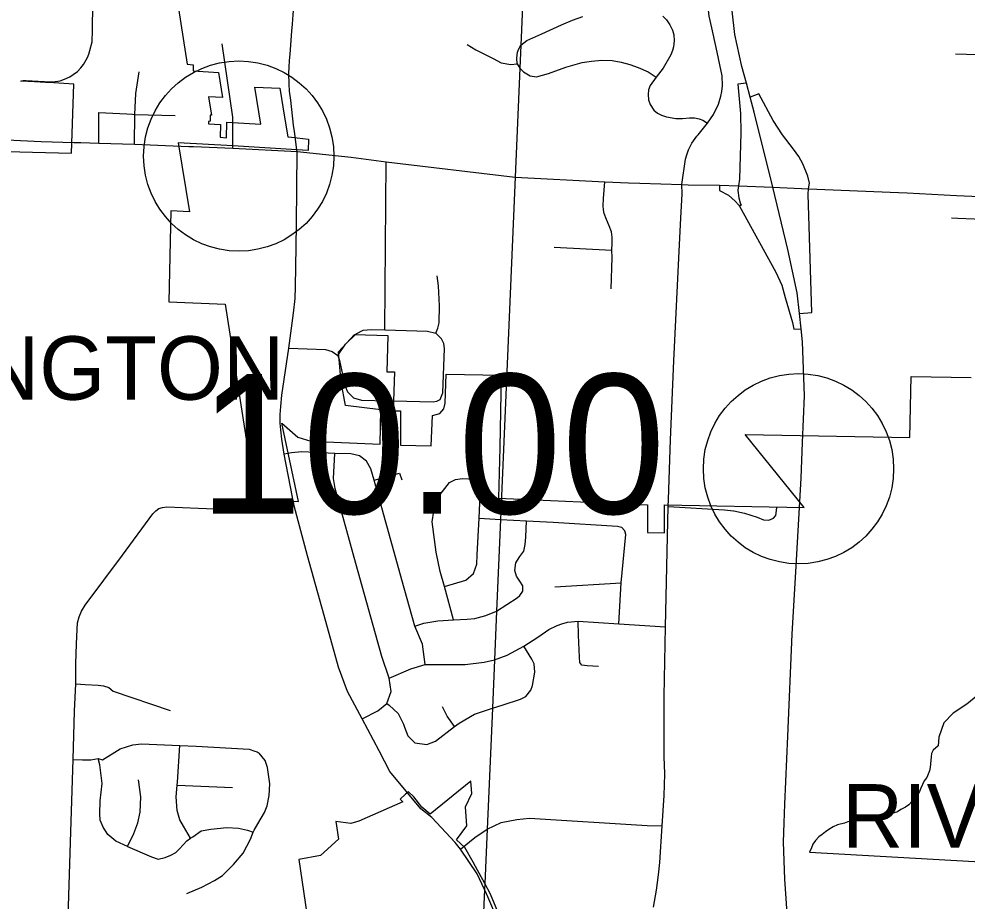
# Model space of a CAD drawing. Extents: x 1729596 to 1934326, y 644115 to 911751.
# Drawn here: x 1812555 to 1820031, y 755846 to 762800 of the extents above; entities that cross this region are included whole.
import ezdxf

# ---------------------------------------------------------------- set-up
doc = ezdxf.new("R2010")
doc.units = 0
for name, color, linetype in [('Default', 7, 'Continuous'), ('GM_X_City_Street', 7, 'Continuous'), ('GM_X_Corporation', 7, 'Continuous'), ('GM_X_Corporation_Text', 7, 'Continuous'), ('GM_X_County_Road', 7, 'Continuous'), ('GM_X_Interchange_Ramps', 7, 'Continuous'), ('GM_X_State_Route', 7, 'Continuous'), ('GM_X_Township', 7, 'Continuous')]:
    doc.layers.add(name, color=color, linetype=linetype)

msp = doc.modelspace()

# ---------------------------------------------------------------- linework, layer by layer
at = {"layer": 'Default'}
for centre in [(1814288, 761719.4), (1818701.8, 759254.1)]:
    msp.add_circle(centre, 750, dxfattribs=at)
at = {"layer": 'GM_X_City_Street'}
for points in [[(1814710.8, 762758.6), (1814716.8, 762832.9), (1814730.6, 763010.5), (1814750.5, 763263.9), (1814758.1, 763336.9), (1814767.3, 763401.8), (1814781.1, 763473.7), (1814798, 763550.3), (1814836.8, 763686.7), (1814871.5, 763796.5), (1814939.9, 763985.4), (1814999.2, 764179.5), (1815163.6, 764672.8), (1815272.9, 764996.6), (1815338.3, 765194.7), (1815458.8, 765550.1), (1815603.2, 765932.7), (1815765.2, 766360), (1815831.4, 766554.7), (1815848.4, 766601.2), (1815849.4, 766604.8)], [(1817910, 761888.1), (1817983.1, 761980.2), (1818032.5, 762047.7), (1818069.8, 762128.4), (1818090.3, 762192.3), (1818096.3, 762229.6), (1818101.2, 762274.2), (1818098.7, 762352.6), (1818053, 762574.3), (1818019.2, 762729.8), (1817997.2, 762822.6), (1817990.4, 762892.8), (1817983.7, 763045.3), (1817993.1, 763139.8), (1818006.6, 763245.1), (1818035, 763373.3), (1818070.1, 763478.6), (1818102.5, 763556.9), (1818143, 763651.4), (1818174, 763748.5), (1818188.9, 763818.7), (1818205.6, 763899.8)], [(1816089.3, 762599), (1816158, 762557.3), (1816294.5, 762488.4), (1816357.2, 762455.7), (1816432.3, 762442.4), (1816483.5, 762447.8), (1816480, 762491), (1816486.1, 762537.8), (1816495.8, 762565.2), (1816511.6, 762593.6), (1816558.5, 762630.5), (1816676.9, 762682.6), (1816834, 762754.2), (1816919.4, 762791.7), (1817001.6, 762820.8)], [(1817632.8, 762821.9), (1817662, 762792.7), (1817687, 762753.1), (1817707.8, 762712.5), (1817718.2, 762676.1), (1817721.3, 762629.2), (1817717.2, 762580.3), (1817708.8, 762551.1), (1817696.3, 762517.8), (1817634.9, 762411.5), (1817579.3, 762341.7), (1817532.3, 762276.7), (1817517.9, 762241.7), (1817515.4, 762205.5), (1817520.2, 762162.2), (1817532.3, 762127.2), (1817561.2, 762082.6), (1817589, 762058.5), (1817620.3, 762041.7), (1817661.3, 762028.4), (1817734.8, 762015.1), (1817787.8, 762015.1), (1817843.2, 762021.1), (1817881.8, 762019.9), (1817918, 762013.9), (1817948.1, 762001.9), (1817983.1, 761980.2)], [(1814727, 761914), (1814720.4, 761962.2), (1814697.5, 762160.2), (1814688.2, 762231.3), (1814684.6, 762289), (1814682.6, 762370.2), (1814685.1, 762420.2), (1814688.2, 762472.3), (1814692.4, 762524.2), (1814706.5, 762705.2), (1814710.8, 762758.6)], [(1819940.7, 762525.7), (1820458.6, 762508.6), (1820575.3, 762563.5), (1820627.5, 762581.1), (1820669.7, 762596.7), (1820725.7, 762596.1), (1820889.5, 762578.5), (1820921.7, 762590.2), (1820969.8, 762603.8), (1821034.1, 762627.1), (1821080.3, 762642.7), (1821182.3, 762635.7), (1821448.1, 762615.1), (1821480.2, 762618.8), (1821504.3, 762634.6), (1821531, 762625.1)], [(1814241.3, 761983.3), (1814242.5, 762026.5), (1814157.7, 762604.1)], [(1816483.5, 762447.8), (1816503.9, 762413.3), (1816532.1, 762382.4), (1816585, 762352.4), (1816634.5, 762345.3), (1816730.7, 762370), (1816866.7, 762419.5), (1816996.5, 762458.4), (1817070.4, 762468.8), (1817150.6, 762475), (1817231.8, 762471.9), (1817303.7, 762459.4), (1817372.4, 762441.7), (1817438.1, 762418.8), (1817516.2, 762384.5), (1817579.3, 762341.7)], [(1813487.2, 762281.2), (1813504, 762384.1)], [(1813464.9, 761812.9), (1813469.2, 762047.3), (1813476.2, 762213.1), (1813487.2, 762281.2)], [(1813184.5, 761820.7), (1813184.4, 762063.2), (1813405.9, 762052.5), (1813448.9, 762049)], [(1813448.9, 762049), (1813469.2, 762047.3), (1813786.9, 762038.6)], [(1814240, 761782.5), (1814240.2, 761799.1), (1814241.3, 761983.3)], [(1814748.7, 761756.5), (1814746.9, 761769.8), (1814727, 761914)], [(1815441, 760350.9), (1815449.3, 761673.2)], [(1817224.2, 760672.2), (1817231.4, 760920.7), (1817230, 760978.9), (1817232.1, 761032.1), (1817232.9, 761080.2), (1817227.8, 761121.5), (1817209.7, 761170.6), (1817186.5, 761219.6), (1817169.3, 761267.7), (1817163.3, 761296.1), (1817162.4, 761326.2), (1817164.1, 761385.6), (1817174.4, 761516.7)], [(1817677.2, 759011.5), (1817693.5, 759481.5), (1817719, 760106), (1817764.1, 761022.2), (1817774.2, 761230.2)], [(1819909.3, 761231.7), (1819957.7, 761229.8), (1820345.4, 761214.8), (1820685.1, 761201.6), (1820733.6, 761199.7)], [(1814714.8, 759012.1), (1814710.8, 759029.7), (1814646.4, 759369.7), (1814628.9, 759488.1), (1814618.8, 759560.8), (1814615.1, 759615.1), (1814614.2, 759681.4), (1814618.8, 759744), (1814628, 759835.1), (1814683.2, 760204.2), (1814720.1, 760482.2), (1814732.9, 760595.4), (1814736.6, 760688.3), (1814740.3, 761005.9), (1814742.3, 761183.5)], [(1816775, 761000.7), (1817230, 760978.9)], [(1815842.2, 760322.7), (1815858.2, 760362.1), (1815868.3, 760403.5), (1815871.3, 760539.1), (1815863, 760696), (1815852.8, 760774.2)], [(1815069.4, 760146.7), (1815129.7, 760236.3), (1815212.9, 760318.4), (1815269.9, 760346), (1815332.8, 760353.5), (1815441, 760350.9)], [(1815441, 760350.9), (1815775.7, 760339.2), (1815842.2, 760322.7)], [(1815876.8, 759801.5), (1815898.4, 759851.9), (1815910.2, 760201.2), (1815905.2, 760242.1), (1815887.5, 760279.4), (1815842.2, 760322.7)], [(1814683.2, 760204.2), (1814971.8, 760193.5), (1815024.8, 760178.9), (1815069.4, 760146.7), (1815081.8, 760108.6), (1815105.5, 759998.5), (1815120.4, 759923.2), (1815144.5, 759861.3), (1815191.9, 759813.4), (1815256.7, 759795.1), (1815462.8, 759789.9), (1815508.3, 759788.7)], [(1815508.3, 759788.7), (1815821.8, 759780.9), (1815851, 759786.8), (1815876.8, 759801.5)], [(1815758.8, 757711.2), (1815736.8, 757871.7), (1815676.2, 758014.1), (1815572.9, 758378.6), (1815356.8, 759164.9), (1815329.6, 759253.8), (1815294.6, 759314.2), (1815238.8, 759356.2), (1815171.1, 759373.2), (1815044.5, 759375.6), (1814784.4, 759386.7), (1814703.5, 759379.6), (1814646.4, 759369.7)], [(1815261.4, 757283.9), (1815384.1, 757345.9), (1815454.7, 757403.4), (1815489.1, 757498.5), (1815475, 757603.5), (1815415.2, 757773.6), (1815211.3, 758506.6), (1815047.4, 759098.6), (1815036.2, 759178.2), (1815044.5, 759375.6)], [(1815910.1, 758327), (1816079.3, 758377), (1816139.3, 758427.6), (1816164.5, 758501.9), (1816168.6, 758576.3), (1816182.7, 758865.2), (1816197.5, 759168.9), (1816200.5, 759228.3), (1816187, 759320.7)], [(1815356.8, 759164.9), (1815556.2, 759219.6), (1815573.2, 759166.7)], [(1815980.8, 758062.3), (1815910.1, 758327), (1815876.2, 758445.1), (1815845.5, 758597.1), (1815812.1, 758835.8), (1815839.4, 759004.3), (1815948.6, 759145), (1815996.4, 759170.9), (1816052.4, 759176.5), (1816197.5, 759168.9)], [(1812940.8, 755638.3), (1812963.4, 756391.7), (1812981.6, 756962.9), (1812993.7, 757342.2), (1813002.4, 757557.5), (1813003.3, 757719), (1813008.5, 757870.9), (1813013.7, 757988.9), (1813016.3, 758039.3), (1813029.3, 758086.1), (1813047.6, 758130.4), (1813077.1, 758179.9), (1813370.5, 758572.3), (1813610.1, 758897.8), (1813633, 758921.9), (1813658.1, 758941.5), (1813685.4, 758950.1), (1813722.1, 758953.3), (1813968.6, 758943.8), (1814165.6, 758936.8), (1814266.3, 758935.1), (1814384.4, 758940.3), (1814626.9, 758950.9), (1814725.5, 758961.1)], [(1815608.8, 756711.7), (1815478.6, 756868.5), (1815394.4, 757030.2), (1815261.4, 757283.9), (1815145.2, 757498.5), (1815075, 757688.9), (1814974, 758050.8), (1814830.5, 758568), (1814725.5, 758961.1), (1814718.6, 758995.9), (1814714.8, 759012.1)], [(1817642.5, 757216.3), (1817641.6, 757462.2), (1817653.5, 758007.1), (1817675.3, 758956.2), (1817677.2, 759011.5)], [(1817675.3, 758956.2), (1818119.1, 758930.7), (1818188.1, 758921.9)], [(1818188.1, 758921.9), (1818191.1, 758921.5), (1818276.7, 758903.3), (1818377, 758872.3), (1818426.2, 758850.5), (1818468.1, 758848.6), (1818504.5, 758865.1), (1818522.8, 758886.9), (1818531.9, 758947.1)], [(1815676.2, 758014.1), (1815747.6, 758036), (1815857.8, 758054.7), (1815980.8, 758062.3), (1816088, 758068.5), (1816148.9, 758075.1), (1816235.5, 758097.6), (1816320.6, 758132.9), (1816483.2, 758236.4), (1816504.9, 758254.1), (1816527.1, 758290.1), (1816527.2, 758332.3), (1816505.1, 758368.4), (1816477.5, 758406.3), (1816463.9, 758451.1), (1816471.7, 758511.5), (1816505.6, 758562.1), (1816536.1, 758605.9), (1816546.7, 758658.2), (1816550.6, 758715.7), (1816557.3, 758843.2)], [(1816182.7, 758865.2), (1816351.6, 758855.3), (1816557.3, 758843.2), (1816767.1, 758832.1), (1817275.5, 758801.8), (1817305.4, 758792.6), (1817333.6, 758765.3)], [(1817285.3, 758030.8), (1817302.6, 758354.3), (1817339, 758737), (1817333.6, 758765.3)], [(1816781.2, 758323.2), (1817302.6, 758354.3)], [(1815475, 757603.5), (1815644.9, 757677.4), (1815758.8, 757711.2), (1815996.4, 757711.9), (1816073.8, 757711.4), (1816224.2, 757729), (1816304.2, 757749), (1816403.3, 757784.1), (1816536.8, 757856.2), (1816645.9, 757927.2), (1816732.3, 757985.9), (1816798.4, 758018.3), (1816834.5, 758030.8), (1816880.7, 758044.5), (1816965.5, 758053.2), (1817285.3, 758030.8), (1817653.5, 758007.1)], [(1817123.8, 757695.2), (1817034, 757700.2), (1816992.9, 757705.2), (1816976.7, 757727.7), (1816975.4, 757770.1), (1816968, 757942.2), (1816965.5, 758053.2)], [(1815454.7, 757403.4), (1815474.6, 757390), (1815545.2, 757325.4), (1815588.2, 757239.8), (1815593.8, 757218.3), (1815622.5, 757148), (1815675.2, 757093.3), (1815771.2, 757079.5), (1815838.8, 757107.3), (1815988.8, 757221.5), (1816027.2, 757249.4), (1816147, 757319.7), (1816287.8, 757367.3), (1816373.8, 757393.4), (1816510, 757439), (1816550.6, 757458.8), (1816590.9, 757507.6), (1816603.6, 757546.8), (1816621.6, 757650.6), (1816618.4, 757716.3), (1816597.7, 757753.2), (1816536.8, 757856.2)], [(1813002.4, 757557.5), (1813078, 757553.2), (1813179.5, 757548), (1813220.3, 757543.6), (1813262.8, 757529.7), (1813298.4, 757502), (1813747.9, 757349.4)], [(1815988.8, 757221.5), (1815931.1, 757304.5), (1815895.8, 757377.3)], [(1817646.9, 756847.2), (1817647.1, 756850.8), (1817643.4, 756983.8), (1817642.5, 757216.3)], [(1812981.6, 756962.9), (1813055.4, 756958.6), (1813120.5, 756958.6), (1813178.7, 756969), (1813213.2, 756959.7), (1813352.8, 757045.4), (1813453.3, 757077.6), (1813521.4, 757086.4), (1813823.1, 757073.9), (1813952.9, 757068.5), (1814370.3, 757042.9), (1814416, 757028), (1814433.8, 757021.7), (1814447.7, 757013.4)], [(1813907.8, 756341.5), (1813851.2, 756437), (1813824.2, 756487.6), (1813803.5, 756560.1), (1813793.5, 756666.6), (1813801.5, 756758.7), (1813803.7, 756784.6), (1813823.1, 757073.9)], [(1814410, 756404.7), (1814439.3, 756454.4), (1814490.9, 756545.6), (1814511.9, 756597.4), (1814527.4, 756679.3), (1814533.1, 756771.3), (1814513.5, 756900), (1814496.5, 756954.4), (1814447.7, 757013.4)], [(1813410.4, 756276.7), (1813319.2, 756318.4), (1813256.2, 756369.7), (1813219.3, 756428.5), (1813196.4, 756483), (1813191.3, 756533.2), (1813195.2, 756637.4), (1813209.8, 756773.4), (1813191.7, 756920.3), (1813178.7, 756969)], [(1813410.4, 756276.7), (1813460.3, 756378), (1813491.9, 756463.6), (1813511.4, 756547.4), (1813515.6, 756667.6), (1813496.2, 756802.3)], [(1817559.5, 755797.1), (1817581.4, 755932.2), (1817597, 756053.4), (1817607.9, 756150), (1817627, 756438.9), (1817641.6, 756677.6), (1817646.9, 756847.2)], [(1813801.5, 756758.7), (1814238.7, 756742.6)], [(1816036.6, 756256.2), (1816149.4, 756347.5), (1816247, 756413.3), (1816357.5, 756465.8), (1816480.3, 756490.1), (1816580.6, 756498.7), (1817507.2, 756443.2), (1817627, 756438.9)], [(1813410.4, 756276.7), (1813598.8, 756195.1), (1813652.4, 756176.1), (1813706.6, 756189.1), (1813753, 756208.3), (1813791.4, 756229.7), (1813821.9, 756257.1), (1813879, 756322.3), (1813907.8, 756341.5), (1813925.6, 756353.5), (1813992.5, 756400.4), (1814068.6, 756413), (1814192.9, 756426.8), (1814284.7, 756421.1), (1814356.4, 756405.8), (1814401.8, 756388.5)], [(1813877.3, 755905.4), (1813998.1, 755955.3), (1814097.1, 756007.6), (1814159.8, 756046.6), (1814247.4, 756133.2), (1814323, 756224), (1814381, 756333.2), (1814401.8, 756388.5), (1814404.1, 756394.9), (1814409.6, 756404), (1814410, 756404.7)]]:
    msp.add_lwpolyline(points, dxfattribs=at)
at = {"layer": 'GM_X_Corporation'}
for points in [[(1813750.9, 763289.6), (1813882.1, 762443.2), (1813929.3, 762439.6), (1813929.7, 762390.5), (1814127.6, 762379.2), (1814159.2, 762182.5), (1814049.7, 762187.2), (1814072.5, 762041.2), (1814063.1, 762041.2), (1814063.5, 761993.5), (1814049.5, 761993.2), (1814048.7, 761973.2), (1814143, 761967.8), (1814140.9, 761867.9), (1814190.1, 761864.4), (1814193.8, 761985.9), (1814461.3, 761971.4), (1814413.7, 762261.8), (1814611, 762254.5), (1814648.4, 762025.9), (1814674.2, 761870.5), (1814702.7, 761868.9), (1814837.9, 761852.1), (1814834.3, 761763.6), (1814746.9, 761769.8), (1814240.2, 761799.1), (1813809, 761823), (1813899.4, 761280.9), (1813752.3, 761286.7), (1813736.5, 760570), (1814181.8, 760551.1), (1814422.1, 758999.2), (1814759.6, 758996.9), (1814627.7, 759613.2), (1814754.2, 759503.5), (1814855.4, 759472.2), (1815402, 759447.2), (1815409.1, 759719.6), (1815129.7, 759752.4), (1815096, 759937.5), (1815073.2, 760175.3), (1815200.2, 760311.5), (1815464.1, 760305.6), (1815454.3, 760018.9), (1815516.5, 760018.1), (1815505.5, 759711.7), (1815562.3, 759710.1), (1815562.3, 759440), (1815804.7, 759434), (1815814.6, 759675.1), (1815874.6, 759690.4), (1815904.8, 759726.1), (1815914.7, 759771.3), (1815924.1, 760000.8), (1816356.9, 759991.3), (1816345.4, 759420.7), (1816337.4, 759022.8), (1817510.2, 758970.3), (1817509.9, 758751.4), (1817644.9, 758748.2), (1817645.5, 758969.1), (1818746.1, 758949.3), (1818280.7, 759524.6), (1819580.5, 759501.3), (1819589.1, 759981.2), (1820064.5, 759972.7)], [(1811638.6, 761776), (1812968.8, 761741.5), (1812988, 762287.5), (1812830.6, 762297.3), (1812764.8, 762300.2), (1812678.5, 762305), (1812570.3, 762310.5), (1812576.6, 762312.4), (1812587.3, 762314), (1812597.9, 762314.3), (1812612.3, 762314.1), (1812802.9, 762304.7), (1812823.2, 762305.2), (1812878.8, 762312.8), (1812915.1, 762325.2), (1812956, 762343.3), (1812983.5, 762361.9), (1813016, 762387.3), (1813043.1, 762416.4), (1813064.1, 762442.2), (1813096, 762497.9), (1813105, 762523.3), (1813113.6, 762551.1), (1813131.6, 762620.5), (1813135, 762708.8), (1813138.3, 762922.9)], [(1820145.7, 757492.5), (1820030.2, 757399.6), (1819921.3, 757328.5), (1819848.6, 757251.1), (1819809, 757139.6), (1819802.4, 757071.1), (1819763.9, 757035.7), (1819751.7, 757009), (1819746.9, 756982.3), (1819742, 756929), (1819739.6, 756899.8), (1819734.7, 756873.2), (1819725, 756846.5), (1819712.9, 756819.8), (1819693.5, 756793.1), (1819679, 756764), (1819666.8, 756737.3), (1819657.1, 756710.7), (1819640.2, 756684), (1819623.2, 756657.3), (1819596.5, 756630.6), (1819572.2, 756603.9), (1819545.6, 756586.9), (1819509.2, 756567.5), (1819482.5, 756550.6), (1819455.8, 756540.8), (1819419.4, 756528.7), (1819392.8, 756516.6), (1819356.4, 756506.9), (1819329.7, 756499.6), (1819295.8, 756494.8), (1819266.7, 756492.3), (1819240, 756489.9), (1819210.9, 756487.5), (1819184.2, 756485), (1819157.5, 756482.6), (1819121.1, 756477.8), (1819092, 756470.5), (1819065.4, 756460.8), (1819009.6, 756446.2), (1818975.6, 756431.7), (1818941.7, 756409.8), (1818915, 756392.9), (1818888.3, 756371), (1818861.6, 756351.6), (1818834.9, 756322.5), (1818815.5, 756295.8), (1818803.4, 756266.7), (1818787.5, 756231.7), (1823340.6, 755973.2)], [(1816424, 755539.8), (1816273.4, 755900.9), (1816228.6, 755985), (1816155.5, 756119.7), (1816136.6, 756152.8), (1816070.5, 756268.4), (1816005.7, 756328.7), (1816085.9, 756439.8), (1816074.9, 756589.4), (1816125, 756693), (1816117.6, 756792.7), (1815797.9, 756531.8), (1815732.4, 756585.7), (1815668.4, 756668.7), (1815627.2, 756708.6), (1815603.7, 756689.9), (1815561.5, 756650), (1815581.8, 756627.9), (1815234, 756477.3), (1815171.7, 756458.9), (1815052.4, 756472.6), (1815075.4, 756334.5), (1814932.9, 756204.3), (1814760.8, 756172.7), (1815125, 753710)]]:
    msp.add_lwpolyline(points, dxfattribs=at)
at = {"layer": 'GM_X_County_Road'}
for points in [[(1817774.2, 761230.2), (1817783.4, 761421.4), (1817780.9, 761494.3), (1817810.6, 761693.9), (1817820.2, 761728.3), (1817835.4, 761769.2), (1817861.9, 761822.1), (1817899.9, 761875.3), (1817910, 761888.1)], [(1814742.3, 761183.5), (1814748.7, 761756.5)], [(1816250.9, 755880.5), (1816241.6, 755902.3), (1816226.5, 755936.1), (1816166.8, 756059.6), (1816036.6, 756256.2), (1815995.5, 756307.7), (1815809.7, 756505.9), (1815724.7, 756572.1), (1815608.8, 756711.7)], [(1816386.3, 755535.1), (1816327.4, 755701.6), (1816250.9, 755880.5)]]:
    msp.add_lwpolyline(points, dxfattribs=at)
at = {"layer": 'GM_X_Interchange_Ramps'}
for points in [[(1818290.4, 762293.7), (1818223.7, 762286.8), (1818243.6, 762054.9), (1818246.9, 761902.4), (1818237.3, 761538), (1818227.5, 761485.2)], [(1818781.8, 761462), (1818787.9, 761505.2), (1818775.4, 761561.7), (1818734.6, 761659), (1818704.8, 761715.5), (1818662.4, 761775.1), (1818574.5, 761888.1), (1818500.8, 761999.5), (1818389.4, 762209.8), (1818320.5, 762184.1)], [(1818077.8, 761489.5), (1818077.6, 761449.1), (1818148.7, 761412.1), (1818202.1, 761364.7), (1818231.7, 761333.5), (1818237, 761323.9), (1818522.1, 760803.2), (1818569.5, 760701), (1818597.6, 760604.7), (1818655.4, 760407.7), (1818665.8, 760354.4), (1818722.3, 760357.2)], [(1818227.5, 761485.2), (1818224, 761449.8), (1818224, 761449.2), (1818230, 761391.3), (1818242, 761350.7), (1818250.6, 761333.4), (1818237, 761323.9)], [(1818709.2, 760477.2), (1818806.4, 760487.4), (1818777.2, 761419.9), (1818781.8, 761462)]]:
    msp.add_lwpolyline(points, dxfattribs=at)
at = {"layer": 'GM_X_State_Route'}
for points in [[(1818498.5, 761474), (1818352.9, 762066.1), (1818320.5, 762184.1), (1818290.4, 762293.7), (1818254.5, 762424.5), (1818200.7, 762677), (1818178, 762864.4), (1818172.6, 763026.4), (1818179.4, 763166.8), (1818188.9, 763291), (1818222.6, 763462.4), (1818256.6, 763605.1), (1818316.8, 763840.3), (1818338.8, 763976), (1818348.5, 764167), (1818350.2, 764250.4), (1818357.7, 764939.8), (1818364, 765374.7), (1818382.6, 765736.3), (1818416.5, 766299.1)], [(1812348.4, 761852.1), (1812728.8, 761833.7), (1812988.5, 761826.9)], [(1812988.5, 761826.9), (1812992.7, 761826.8), (1813041.9, 761825.3)], [(1813041.9, 761825.3), (1813184.5, 761820.7), (1813464.9, 761812.9), (1813895.5, 761796.1)], [(1813895.5, 761796.1), (1813930.2, 761794.7), (1814240, 761782.5), (1814748.7, 761756.5), (1815174.9, 761709.6), (1815449.3, 761673.2), (1816467, 761552), (1817174.4, 761516.7), (1817361.1, 761509.2)], [(1817361.1, 761509.2), (1817450.1, 761505.6), (1817780.9, 761494.3), (1817830.4, 761493.5)], [(1817830.4, 761493.5), (1818077.8, 761489.5), (1818227.5, 761485.2), (1818498.5, 761474)], [(1818498.5, 761474), (1818781.8, 761462), (1819490.9, 761431.9)], [(1818709.2, 760477.2), (1818691.2, 760641.2), (1818617.5, 760983.9), (1818498.5, 761474)], [(1819490.9, 761431.9), (1819557.6, 761429.1), (1819946.7, 761409.8)], [(1819946.7, 761409.8), (1820367, 761389), (1821082.9, 761360.7), (1822391.1, 761300.8), (1822428.3, 761297)], [(1818734.3, 759462.6), (1818749.2, 759829.2), (1818733.4, 760256.3), (1818722.3, 760357.2), (1818709.2, 760477.2)], [(1818617.3, 757147.3), (1818651.6, 757950.1), (1818680.7, 758442.4), (1818722.9, 759180.6), (1818734.3, 759462.6)], [(1818588.7, 756463), (1818594.3, 756609.3), (1818617.3, 757147.3)], [(1818632.4, 755569.4), (1818617.2, 755675.5), (1818594.3, 756019.2), (1818582.9, 756311.4), (1818588.7, 756463)]]:
    msp.add_lwpolyline(points, dxfattribs=at)
at = {"layer": 'GM_X_Township'}
msp.add_lwpolyline([(1816579.8, 764185.6), (1816511.6, 762593.6), (1816503.9, 762413.3), (1816467, 761552), (1816351.5, 758855.3), (1816320.6, 758132.9), (1816304.2, 757749), (1816287.8, 757367.3), (1816247, 756413.3), (1816228.6, 755985), (1816226.5, 755936.1), (1816215.7, 755699.8), (1816132.7, 753880.3), (1816126.1, 753823), (1816118, 753735.6), (1816045.3, 751981.4), (1815895.5, 748206), (1815879.3, 747871.6), (1815796.2, 746156.8)], dxfattribs=at)

# ---------------------------------------------------------------- texts
at = {"layer": 'Default'}
msp.add_text('10.00', height=1100, dxfattribs=at).set_placement((1813971.9, 758900.6))
at = {"layer": 'GM_X_Corporation_Text'}
for s, p in [('WORTHINGTON', (1809520.7, 759798.5)), ('RIVERLEA', (1819043.9, 756267.8))]:
    msp.add_text(s, height=500, rotation=0.00001, dxfattribs=at).set_placement(p)

doc.saveas('drawing.dxf')
